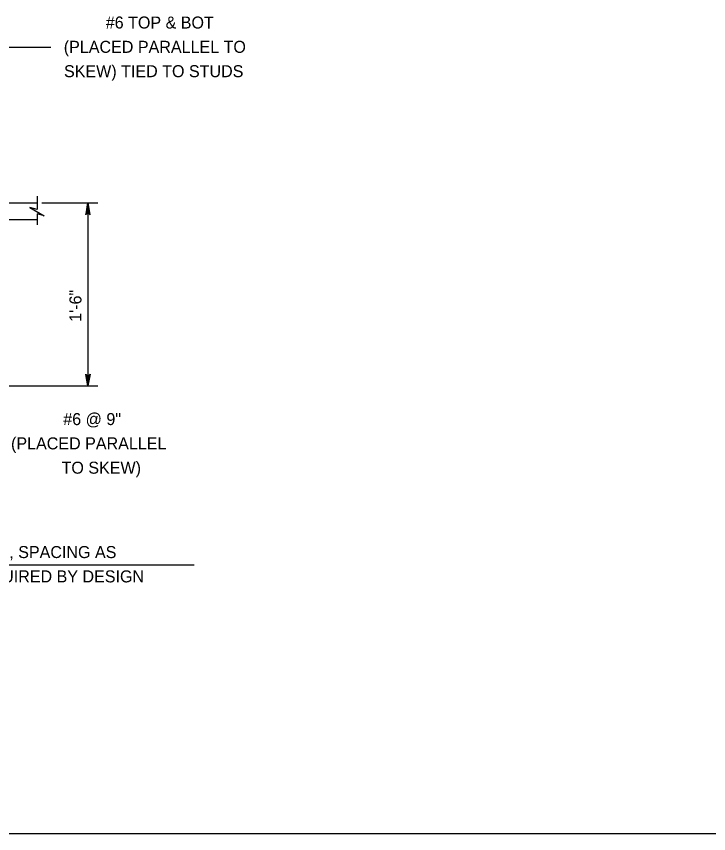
# Model space of a CAD drawing. Extents: x 636530 to 644067, y 294168 to 299122.
# Drawn here: x 639390.6 to 639563.5, y 294777.5 to 294981.6 of the extents above; entities that cross this region are included whole.
import ezdxf

# ---------------------------------------------------------------- set-up
doc = ezdxf.new("R2010")
doc.units = 0
doc.layers.add('1', color=7, linetype='Continuous')

msp = doc.modelspace()

# ---------------------------------------------------------------- linework, layer by layer
at = {"layer": '1'}
for p, q in [((639399.25, 294973.79), (639356.73, 294973.79)), ((639395.88, 294936.7), (639395.88, 294933.31)), ((639358.15, 294934.99), (639395.88, 294934.99)), ((639395.88, 294933.31), (639393.98, 294933.8)), ((639393.98, 294933.8), (639397.59, 294931.75)), ((639396.97, 294934.99), (639410.98, 294934.99)), ((639408.52, 294934.99), (639408.52, 294889.27)), ((639397.59, 294931.75), (639395.88, 294932.28)), ((639395.88, 294932.28), (639395.88, 294929.48)), ((639358.15, 294930.86), (639395.88, 294930.86)), ((639385.47, 294889.27), (639410.98, 294889.27)), ((639367.47, 294844.59), (639435.03, 294844.59)), ((639046.78, 294777.48), (639832.78, 294777.48))]:
    msp.add_line(p, q, dxfattribs=at)
for points in [[(639408.52, 294934.99), (639407.96, 294932.01), (639408.04, 294932.12), (639408.12, 294932.24), (639408.22, 294932.3), (639408.32, 294932.35), (639408.42, 294932.37), (639408.52, 294932.39), (639408.62, 294932.37), (639408.72, 294932.35), (639408.82, 294932.3), (639408.92, 294932.24), (639409, 294932.12), (639409.08, 294932.01), (639408.52, 294934.99), (639409, 294932.12), (639408.92, 294932.24), (639408.52, 294934.99), (639408.82, 294932.3), (639408.72, 294932.35), (639408.52, 294934.99), (639408.62, 294932.37), (639408.52, 294932.39), (639408.52, 294934.99), (639408.42, 294932.37), (639408.32, 294932.35), (639408.52, 294934.99), (639408.22, 294932.3), (639408.12, 294932.24), (639408.52, 294934.99), (639408.04, 294932.12)], [(639408.52, 294889.27), (639407.96, 294892.25), (639408.04, 294892.14), (639408.12, 294892.02), (639408.22, 294891.96), (639408.32, 294891.9), (639408.42, 294891.89), (639408.52, 294891.87), (639408.62, 294891.89), (639408.72, 294891.9), (639408.82, 294891.96), (639408.92, 294892.02), (639409, 294892.14), (639409.08, 294892.25), (639408.52, 294889.27), (639409, 294892.14), (639408.92, 294892.02), (639408.52, 294889.27), (639408.82, 294891.96), (639408.72, 294891.9), (639408.52, 294889.27), (639408.62, 294891.89), (639408.52, 294891.87), (639408.52, 294889.27), (639408.42, 294891.89), (639408.32, 294891.9), (639408.52, 294889.27), (639408.22, 294891.96), (639408.12, 294892.02), (639408.52, 294889.27), (639408.04, 294892.14)]]:
    msp.add_lwpolyline(points, dxfattribs=at)

# ---------------------------------------------------------------- texts
for s, p in [('#6 TOP & BOT', (639412.98, 294978.52)), ('(PLACED PARALLEL TO', (639402.49, 294972.45)), ('SKEW) TIED TO STUDS', (639402.55, 294966.37)), ('#6 @ 9"', (639402.37, 294879.5)), ('(PLACED PARALLEL', (639389.32, 294873.43)), ('TO SKEW)', (639401.94, 294867.36)), ('#6, SPACING AS', (639384.42, 294846.29)), ('REQUIRED BY DESIGN', (639378.41, 294840.22))]:
    msp.add_text(s, height=3, dxfattribs=at).set_placement(p)
msp.add_text('1\'-6"', height=3, rotation=90, dxfattribs=at).set_placement((639406.9, 294905.28))

doc.saveas('drawing.dxf')
